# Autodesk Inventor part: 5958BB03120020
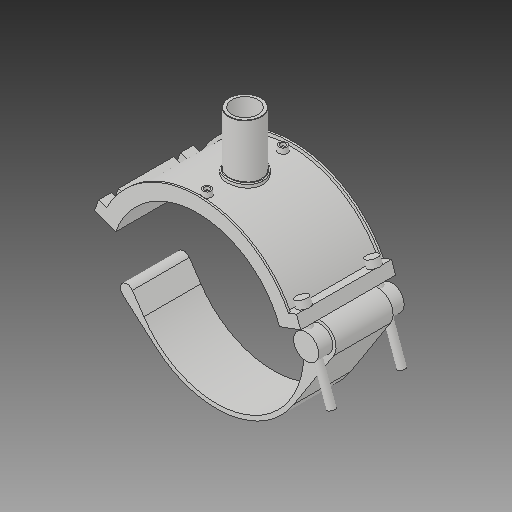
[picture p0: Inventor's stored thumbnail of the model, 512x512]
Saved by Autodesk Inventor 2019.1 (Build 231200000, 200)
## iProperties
Created: 2017-07
Part Number: 5958BB03120020
Material: Generic
Description: PLASSON BRANCH SADDLE 12'' x 2''
Document SubType Name: Modeling
Designer: KIM
Mass: 764.267 g
Surface Area: 1930.38 cm^2
Volume: 764.267 cm^3
Density: 1 g/cm^3
Appearance: Default
Author: KIM
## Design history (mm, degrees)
derived "5958B.ipt"
feature "Solid1::5958B.ipt"
feature "Solid2::5958B.ipt"
feature "Solid3::5958B.ipt"
tag "TaggingFeature1"
body "Solid1"
body "Solid2"
body "Solid3"
other parameters: "d_" = 323.4, "B_" = 180.594, "H_" = 104.902, "L_" = 176.022, "d_t" = 6, "d_1" = 60.1, "H_1" = 84.074, "d1" = 365.056, "d148" = 8.085, "d160" = 8.085, "d0" = 323.4, "d2" = 234.7722, "d3" = 80.85, "d4" = 176.022, "d5" = 0, "d6" = 0.1, "d8" = 0, "d19" = 6, "d20" = 6, "d21" = 105.6132, "d23" = 0, "d24" = 52.8066, "d26" = 0, "d27" = 3, "d28" = 3, "d29" = 3, "d30" = 107.8, "d31" = 6, "d32" = 0, "d33" = 0, "d34" = 0.6, "d40" = 189.82912, "d41" = 66.11, "d43" = 0, "d45" = 0, "d47" = 287.43, "d48" = 60.1, "d50" = 0, "d70" = 15, "d72" = 0, "d73" = 6, "d75" = 5, "d76" = 0, "d77" = 16.17, "d78" = 191.7, "d79" = 15, "d80" = 70.4088, "d82" = 5 deg, "d84" = 4, "d85" = 14, "d86" = 0, "d87" = 3, "d88" = 0, "d89" = 1, "d90" = 1, "d91" = 140.8176, "d92" = 0, "d93" = 0.5, "d94" = 170.21053, "d96" = 372.35712, "d97" = 3.52044, "d98" = 0, "d102" = 1.803, "d103" = 48.08, "d105" = 0, "d109" = -34.96733, "d117" = 0.601, "d120" = 140 deg, "d121" = 24.228, "d122" = 20 deg, "d123" = 730.112, "d124" = 219.0336, "d126" = 0, "d143" = 339.57, "d150" = 58.212, "d159" = 8.3312, "d161" = 8.085, "d162" = 105.6132, "d163" = 0, "d167" = 64.68, "d168" = 165.93455, "d173" = 1, "d175" = 161.7, "d176" = 20 deg, "d177" = 22.638, "d178" = 41.656, "d180" = 0, "d185" = 57.20715, "d186" = 57.20715, "d187" = 182.528, "d188" = 12.4968, "d189" = 22.638, "d190" = 0, "d191" = 273.792, "d200" = 20.828, "d202" = 0, "d216" = 158.4198, "d217" = 0, "d221" = 65.12814, "d222" = 22.638, "d223" = 13.5828, "d224" = 161.7, "d225" = 13.5828, "d227" = 46.5696, "d230" = 192.423, "d236" = 11.5 deg, "d238" = 20 deg, "d239" = 22.638, "d240" = 3.52044, "d241" = 0, "d242" = 6.468
